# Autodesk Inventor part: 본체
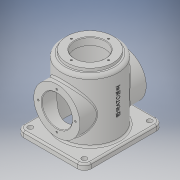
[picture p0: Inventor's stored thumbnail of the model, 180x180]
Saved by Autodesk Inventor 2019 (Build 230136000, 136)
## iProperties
Created: 2020-12
Part Number: 본체
Material: 일반
Document SubType Name: Modeling
Designer: jun-1-3
Mass: 456.569 g
Surface Area: 1073.84 cm^2
Volume: 456.569 cm^3
Density: 1 g/cm^3
Appearance: 기본값
Author: jun-1-3
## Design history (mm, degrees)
sketch "스케치1"
  geometry: L1 (60, 70)-(-60, 70); L2 (-60, 70)-(-60, -70); L3 (-60, -70)-(60, -70); L4 (60, -70)-(60, 70); L5 (60, 70)-(-60, -70); L6 (-60, 70)-(60, -70); 1 further point
  constraints: 12 end point, 2 midpoint, 2 parallel, 1 horizontal, 1 perpendicular
  dimensions: "d0" = 120 distance of L3.end L2.end; "d1" = 140 distance of L2.end L1.end
extrude "돌출1" new body sketch "스케치1" distance "d2" = 10; taper "d3" = 0 deg
sketch "스케치2"
  geometry: C1 r 50 at (0, 0); 1 further point
  constraints: 1 centre point, 1 coincident
  dimensions: "d4" = 100 diameter of C1
extrude "돌출2" join sketch "스케치2" distance "d5" = 120; taper "d6" = 0 deg
sketch "스케치3"
  geometry: C1 r 41 at (0, 0); 1 further point
  constraints: 1 centre point, 1 coincident
  dimensions: "d7" = 82 diameter of C1
extrude "돌출3" join sketch "스케치3" distance "d8" = 5; taper "d9" = 0 deg
node "작업 평면1"
sketch "스케치4"
  geometry: L1 (-60, 0)-(60, 0) reference; C1 r 41 at (0, 60); 2 further points
  constraints: 1 centre point, 1 midpoint, 1 vertical alignment
  dimensions: "d11" = 82 diameter of C1; "d12" = 60 distance from line of L1 C1.centre
extrude "돌출4" join sketch "스케치4" stored distance "d13" = 5; taper "d14" = 0 deg
sketch "스케치5" dims "d15" = 66
  geometry: C1 r 41 at (0, 0) reference; 3 further points
  constraints: 2 vertical alignment, 3 other
hole "구멍1" sketch "스케치5" at (0, 33) diameter "d16" = 3.242; stored, may be unused: countersink angle "d20" = 90 deg, drill point angle "d22" = 118 deg; dims "d17" = 8, "d18" = 4, "d19" = 2, "d21" = 10
sketch "스케치6"
  geometry: C1 r 41 at (0, 0) reference; 2 further points
  constraints: 1 coincident
hole "구멍2" sketch "스케치6" at (0, 0) diameter "d26" = 54; stored, may be unused: countersink angle "d30" = 90 deg, drill point angle "d32" = 118 deg; dims "d27" = 8, "d28" = 4, "d29" = 2, "d31" = 10
sketch "스케치7" dims "d33" = 66
  geometry: 3 further points
  constraints: 2 horizontal alignment, 1 coincident, 2 other
hole "구멍3" sketch "스케치7" at (-33, 0) diameter "d34" = 3.242; stored, may be unused: countersink angle "d38" = 90 deg, drill point angle "d40" = 118 deg; dims "d35" = 8, "d36" = 4, "d37" = 2, "d39" = 10
sketch "스케치8"
  geometry: C1 r 41 at (0, 0) reference; 2 further points
  constraints: 1 coincident
hole "구멍4" sketch "스케치8" at (0, 0) diameter "d44" = 54; stored, may be unused: countersink angle "d48" = 90 deg, drill point angle "d50" = 118 deg; dims "d45" = 8, "d46" = 4, "d47" = 2, "d49" = 10
sketch "스케치9"
  geometry: C1 r 42 at (0, 0); 1 further point
  constraints: 1 centre point, 1 coincident
  dimensions: "d51" = 84 diameter of C1
extrude "돌출5" cut sketch "스케치9" distance "d52" = 112; taper "d53" = 0 deg
fillet "모깎기1" dims "d54" = 12
sketch "스케치10"
  geometry: A1 r 12 centre (-48, 58) between (-48, 70) and (-60, 58) reference; A2 r 12 centre (-48, -58) between (-60, -58) and (-48, -70) reference; A3 r 12 centre (48, -58) between (48, -70) and (60, -58) reference; A4 r 12 centre (48, 58) between (60, 58) and (48, 70) reference; 5 further points
  constraints: 4 coincident
hole "구멍5" sketch "스케치10" at (-48, 58), (-48, -58), (48, -58), (48, 58) diameter "d55" = 9; stored, may be unused: countersink angle "d59" = 90 deg, drill point angle "d61" = 118 deg; dims "d56" = 8, "d57" = 4, "d58" = 2, "d60" = 10
node "작업 평면2"
sketch "스케치11"
  geometry: L1 (0, 58)-(0, -58) reference; L2 (45.795, 3.868)-(95.57, 3.868); L3 (95.57, 3.868)-(95.57, -3.337); L4 (95.57, -3.337)-(45.795, -3.337); L5 (45.795, -3.337)-(45.795, 3.868); 3 further points
  constraints: 1 horizontal alignment, 1 midpoint, 2 other
  dimensions: "d63" = 70 distance from line of L1 point (70, 0)
feature "엠보싱1" sketch "스케치11" dims "d0" = 120, "d1" = 140, "d64" = 0.5, "d65" = 0
fillet "모깎기2" dims "d66" = 3
fillet "모깎기3" dims "d67" = 6
chamfer "모따기1" distance "d68" = 1; stored, may be unused: second distance "d69" = 2, angle "d70" = 45 deg
node "솔리드1"
pattern_circular "원형 패턴1" dims angle "d24" = 360 deg
mirror "미러1"
pattern_circular "원형 패턴2" dims angle "d42" = 360 deg
other parameters: "d10" = 59
